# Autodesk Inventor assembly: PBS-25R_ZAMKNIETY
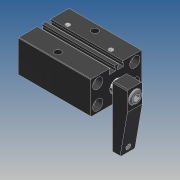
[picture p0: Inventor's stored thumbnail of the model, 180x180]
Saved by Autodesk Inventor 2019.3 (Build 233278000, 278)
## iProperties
Created: 2010-02
Part Number: PBS-25R_ZAMKNIETY
Material: Ogólny
Document SubType Name: Assembly
Designer: CADENGINEERING4
Sending System: PRO/ENGINEER BY PARAMETRIC TECHNOLOGY CORPORATION, 2007170
Preprocessor: PRO/ENGINEER BY PARAMETRIC TECHNOLOGY CORPORATION, 2007170
Title: PSB-25_ASM
Author: Administrator
Revision Number: 1LAST_VERSION
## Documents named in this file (6)
- E:\SERWER_ZAPAS\Pneumatic\PSB PNEUMATIC SWING\PSB-25\PBS-25R_ZAMKNIETY.iam
- E:\SERWER_ZAPAS\Pneumatic\PSB PNEUMATIC SWING\PSB-25\PSB-25BT.ipt
- E:\SERWER_ZAPAS\Pneumatic\PSB PNEUMATIC SWING\PSB-25\PSB-25HSG.ipt
- E:\SERWER_ZAPAS\Pneumatic\PSB PNEUMATIC SWING\PSB-25\PSB-25HG.ipt
- E:\SERWER_ZAPAS\Pneumatic\PSB PNEUMATIC SWING\PSB-25\PSB-25YB.ipt
- E:\SERWER_ZAPAS\Pneumatic\PSB PNEUMATIC SWING\PSB-25\M8X20.ipt
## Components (5 placed, 5 different names)
1. PSB-25BT_0 — Równoległe:1, Zestawiające:1, Zestawiające:2, Kątowe:1
2. PSB-25HSG_1 — Zestawiające:2, Zestawiające:4, Zestawiające:5, Zestawiające:8
3. PSB-25HG_2 — Równoległe:1, Zestawiające:1, Zestawiające:8
4. PSB-25YB_3 — Zestawiające:4, Zestawiające:5, Zestawiające:6, Zestawiające:7, Kątowe:1
5. M8X20_4 — Zestawiające:6, Zestawiające:7
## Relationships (9: Mate 7, Flush 1, Angle 1)
- Równoległe:1 [Flush]: PSB-25BT_0 ↔ PSB-25HG_2
- Zestawiające:1 [Mate]: PSB-25BT_0 ↔ PSB-25HG_2
- Zestawiające:2 [Mate]: PSB-25BT_0 ↔ PSB-25HSG_1
- Zestawiające:4 [Mate]: PSB-25HSG_1 ↔ PSB-25YB_3
- Zestawiające:5 [Mate]: PSB-25HSG_1 ↔ PSB-25YB_3
- Zestawiające:6 [Mate]: PSB-25YB_3 ↔ M8X20_4
- Zestawiające:7 [Mate]: PSB-25YB_3 ↔ M8X20_4
- Kątowe:1 [Angle]: PSB-25BT_0 ↔ PSB-25YB_3
- Zestawiające:8 [Mate]: PSB-25HSG_1 ↔ PSB-25HG_2
